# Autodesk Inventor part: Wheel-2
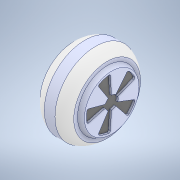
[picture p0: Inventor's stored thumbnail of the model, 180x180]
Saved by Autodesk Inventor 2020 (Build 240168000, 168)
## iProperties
Created: 2020-04
Part Number: Wheel-2
Material: Générique
Document SubType Name: Modeling
Designer: bruno
Density: 1 g/cm^3
Appearance: Par défaut
Mass: 1299.53 g
Surface Area: 678.535 cm^2
Volume: 1299.53 cm^3
Sending System: SolidWorks 2017
Last Author: hpras
Last Saved: 2020-04-23
Author: bruno
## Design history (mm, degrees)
feature "CirPattern2"
sketch "Esquisse1"
  geometry: C1 r 12.7 at (0, 0); A1 r 12.7 centre (0, 0) between (6.917, -10.651) and (11.413, -5.57) reference; A2 r 12.7 centre (0, 0) between (-7.992, -9.87) and (0.665, -12.683) reference; A3 r 12.7 centre (0, 0) between (-11.856, 4.551) and (-11.856, -4.551) reference; A4 r 12.7 centre (0, 0) between (0.665, 12.683) and (-7.992, 9.87) reference; A5 r 12.7 centre (0, 0) between (11.413, 5.57) and (6.917, 10.651) reference; 11 further points
  constraints: 1 centre point, 1 coincident, 1 concentric
extrude "Extrusion1" join sketch "Esquisse1" distance "d0" = 10; taper "d1" = 0 deg
chamfer "Chanfrein1" distance "d2" = 0.5; stored, may be unused: second distance "d3" = 2, angle "d4" = 45 deg
sketch "Esquisse2"
  geometry: L1 (15.777, 80)-(-33.547, 80); L2 (-33.547, 80)-(-33.547, 89.418); L3 (-33.547, 89.418)-(15.777, 89.418); L4 (15.777, 89.418)-(15.777, 80); L5 (0, 0)-(49.987, 0)
  constraints: 10 end point, 2 horizontal, 2 parallel, 1 perpendicular
  dimensions: "d5" = 80 distance from line of L1 L5.start
revolve "Révolution1" sketch "Esquisse2" stored, may be unused: angle "d6" = 90 deg
node "Solide1"
